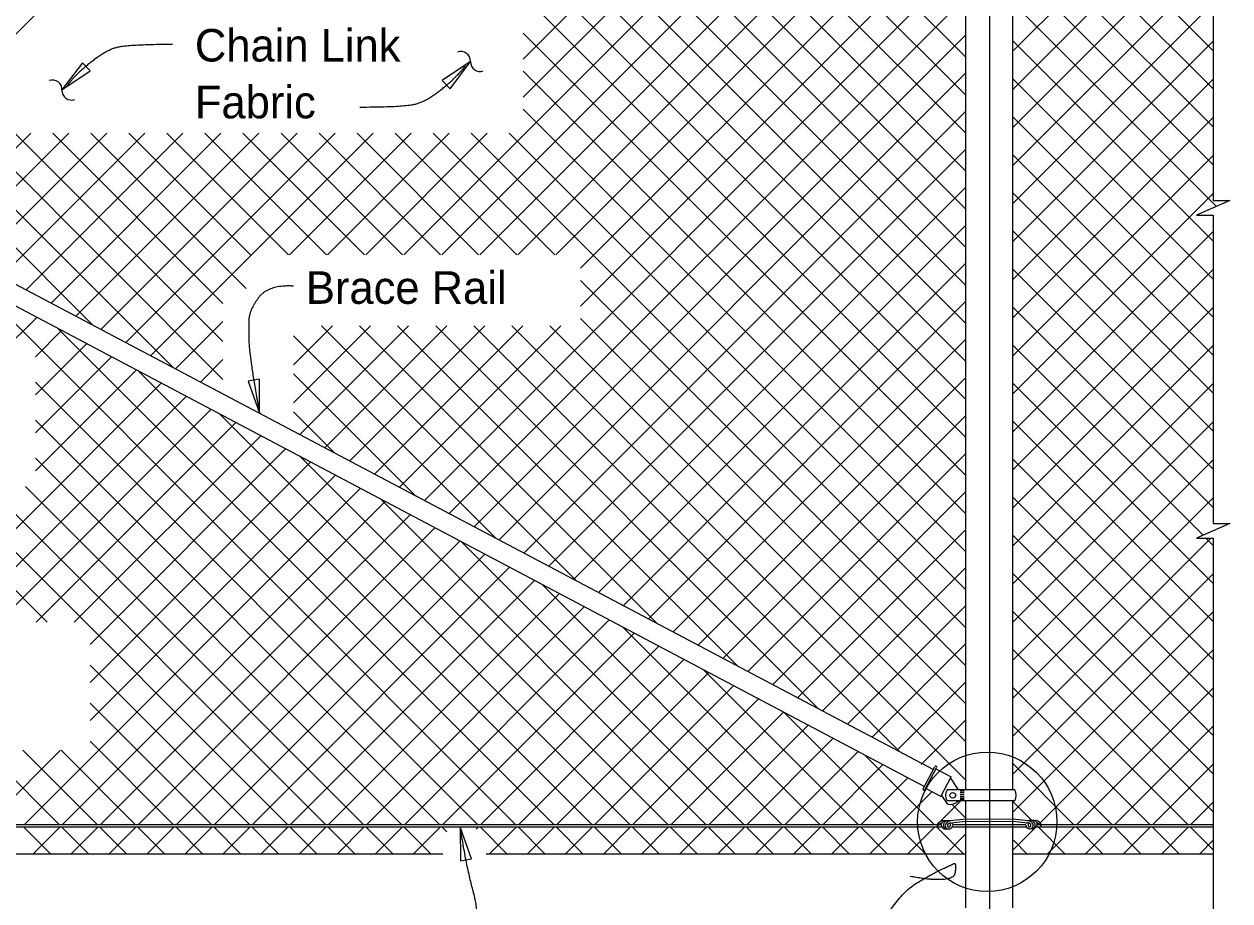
# Model space of a CAD drawing. Extents: x 0 to 72.1, y -7 to 30.
# Drawn here: x 16.24 to 23.71, y 18.9 to 24.33 of the extents above; entities that cross this region are included whole.
import ezdxf

# ---------------------------------------------------------------- set-up
doc = ezdxf.new("R2010")
doc.units = 0
for name, color, linetype in [('AdhocPoint_dp', 7, 'Continuous'), ('Border', 7, 'Continuous'), ('Patterning', 7, 'Continuous'), ('PlotBorder_dp', 7, 'Continuous'), ('SheetBorder_dp', 7, 'Continuous'), ('TextMisc', 7, 'Continuous'), ('TextStructures', 7, 'Continuous')]:
    doc.layers.add(name, color=color, linetype=linetype)

msp = doc.modelspace()

# ---------------------------------------------------------------- linework, layer by layer
at = {"layer": 'AdhocPoint_dp'}
for p, q in [((14.1214, 25.0085), (16.6644, 22.4655)), ((14.3571, 25.0085), (17.1643, 22.2013)), ((14.5928, 25.0085), (17.4733, 22.128)), ((14.8285, 25.0085), (17.4733, 22.3637)), ((15.1745, 23.2529), (16.9301, 25.0085)), ((18.5935, 22.9006), (20.7014, 25.0085)), ((18.8292, 22.9006), (20.9371, 25.0085)), ((18.8354, 25.0085), (22.0764, 21.7675)), ((19.0649, 22.9006), (21.1728, 25.0085)), ((19.0711, 25.0085), (22.0764, 22.0032)), ((19.3006, 22.9006), (21.4085, 25.0085)), ((19.3068, 25.0085), (22.0764, 22.2389)), ((19.3344, 23.8772), (20.4657, 25.0085)), ((19.3344, 24.1129), (20.23, 25.0085)), ((19.5363, 22.9006), (21.6442, 25.0085)), ((19.5363, 22.9006), (21.6442, 25.0085)), ((19.5425, 25.0085), (22.0764, 22.4746)), ((19.6891, 22.8178), (21.8799, 25.0085)), ((19.6891, 22.582), (22.0764, 24.9694)), ((19.7782, 25.0085), (22.0764, 22.7103)), ((20.0139, 25.0085), (22.0764, 22.946)), ((20.2496, 25.0085), (22.0764, 23.1818)), ((20.4853, 25.0085), (22.0764, 23.4175)), ((20.721, 25.0085), (22.0764, 23.6532)), ((20.9567, 25.0085), (22.0764, 23.8889)), ((21.1925, 25.0085), (22.0764, 24.1246)), ((22.3681, 23.9248), (23.4518, 25.0085)), ((22.3725, 24.165), (23.2161, 25.0085)), ((22.5286, 25.0085), (23.6092, 23.928)), ((22.7643, 25.0085), (23.6092, 24.1637)), ((22.3681, 24.9334), (23.6092, 23.6923)), ((22.3681, 23.6891), (23.6092, 24.9302)), ((18.7213, 21.3785), (22.0764, 24.7337)), ((22.3681, 24.6977), (23.6092, 23.4566)), ((22.3681, 23.4534), (23.6092, 24.6945)), ((18.8755, 21.297), (22.0764, 24.4979)), ((22.3681, 24.462), (23.6302, 23.1998)), ((22.3681, 23.2177), (23.6092, 24.4588)), ((19.0297, 21.2155), (22.0764, 24.2622)), ((19.3344, 24.2739), (22.0764, 21.5318)), ((22.3681, 24.2263), (23.6092, 22.9852)), ((22.3681, 22.982), (23.6092, 24.2231)), ((19.1839, 21.134), (22.0764, 24.0265)), ((19.3344, 24.0382), (22.0764, 21.2961)), ((22.3681, 23.9906), (23.6092, 22.7495)), ((22.3681, 22.7463), (23.6092, 23.9874)), ((19.3344, 23.8025), (22.0764, 21.0604)), ((19.3381, 21.0525), (22.0764, 23.7908)), ((22.3681, 23.7549), (23.6092, 22.5138)), ((22.3681, 22.5106), (23.6092, 23.7517)), ((15.6371, 23.0084), (16.2825, 23.6538)), ((15.7913, 22.9269), (16.5182, 23.6538)), ((15.7913, 22.9269), (16.5182, 23.6538)), ((15.9455, 22.8454), (16.7539, 23.6538)), ((15.9455, 22.8454), (16.7539, 23.6538)), ((16.0997, 22.7639), (16.9896, 23.6538)), ((16.0997, 22.7639), (16.9896, 23.6538)), ((16.2539, 22.6824), (17.2253, 23.6538)), ((16.2539, 22.6824), (17.2253, 23.6538)), ((16.4081, 22.6009), (17.461, 23.6538)), ((16.4189, 23.6538), (17.4733, 22.5994)), ((16.5623, 22.5194), (17.6967, 23.6538)), ((16.6546, 23.6538), (17.6177, 22.6907)), ((16.7166, 22.4379), (17.9324, 23.6538)), ((16.8708, 22.3564), (18.1681, 23.6538)), ((16.8903, 23.6538), (17.6435, 22.9006)), ((16.8903, 23.6538), (17.6435, 22.9006)), ((17.025, 22.2749), (18.4038, 23.6538)), ((17.126, 23.6538), (17.8792, 22.9006)), ((17.3617, 23.6538), (18.1149, 22.9006)), ((17.3617, 23.6538), (18.1149, 22.9006)), ((17.3617, 23.6538), (18.1149, 22.9006)), ((17.5974, 23.6538), (18.3506, 22.9006)), ((17.5974, 23.6538), (18.3506, 22.9006)), ((17.8331, 23.6538), (18.5863, 22.9006)), ((17.8864, 22.9006), (18.6395, 23.6538)), ((18.0688, 23.6538), (18.822, 22.9006)), ((18.1221, 22.9006), (18.8752, 23.6538)), ((18.3045, 23.6538), (19.0577, 22.9006)), ((18.3578, 22.9006), (19.1109, 23.6538)), ((18.5402, 23.6538), (19.2934, 22.9006)), ((18.7759, 23.6538), (19.5291, 22.9006)), ((19.0116, 23.6538), (22.0764, 20.589)), ((19.2473, 23.6538), (22.0764, 20.8247)), ((19.4923, 20.9711), (22.0764, 23.5551)), ((22.3681, 23.5192), (23.6092, 22.2781)), ((22.3681, 22.2749), (23.6092, 23.516)), ((19.6465, 20.8896), (22.0764, 23.3194)), ((22.3681, 23.2835), (23.6092, 22.0424)), ((22.3681, 22.0392), (23.6092, 23.2803)), ((19.8007, 20.8081), (22.0764, 23.0837)), ((22.3681, 23.0478), (23.6092, 21.8067)), ((22.3681, 21.8035), (23.6092, 23.0446)), ((19.9549, 20.7266), (22.0764, 22.848)), ((22.3681, 22.8121), (23.6092, 21.571)), ((22.3681, 21.5678), (23.6092, 22.8089)), ((19.6891, 22.7406), (22.0764, 20.3533)), ((15.9523, 22.7062), (19.2871, 19.3714)), ((20.1092, 20.6451), (22.0764, 22.6123)), ((22.3681, 22.5764), (23.6092, 21.3353)), ((22.3681, 21.3321), (23.6092, 22.5732)), ((16.1061, 22.2989), (16.3194, 22.5122)), ((19.6891, 22.5049), (22.0764, 20.1176)), ((16.3112, 22.2683), (16.4736, 22.4307)), ((16.4522, 22.442), (19.5228, 19.3714)), ((17.1792, 22.1934), (17.4733, 22.4876)), ((17.9108, 21.9823), (18.3883, 22.4597)), ((17.9108, 22.218), (18.1526, 22.4597)), ((17.9502, 21.786), (18.624, 22.4597)), ((18.0844, 22.4597), (19.6635, 20.8806)), ((18.0844, 22.4597), (19.6635, 20.8806)), ((18.1044, 21.7045), (18.8597, 22.4597)), ((18.2586, 21.623), (19.0954, 22.4597)), ((18.2586, 21.623), (19.0954, 22.4597)), ((18.3201, 22.4597), (20.1634, 20.6164)), ((18.4129, 21.5415), (19.3311, 22.4597)), ((18.5558, 22.4597), (20.6633, 20.3523)), ((18.5558, 22.4597), (20.6633, 20.3523)), ((18.5558, 22.4597), (20.6633, 20.3523)), ((18.5671, 21.46), (19.5668, 22.4597)), ((18.7915, 22.4597), (21.1631, 20.0881)), ((18.7915, 22.4597), (21.1631, 20.0881)), ((19.0272, 22.4597), (21.663, 19.824)), ((19.2629, 22.4597), (22.0764, 19.6462)), ((19.4986, 22.4597), (22.0764, 19.8819)), ((16.3112, 22.0326), (16.6278, 22.3492)), ((17.9108, 22.3976), (19.1637, 21.1447)), ((20.2634, 20.5636), (22.0764, 22.3766)), ((22.3681, 22.3406), (23.5466, 21.1621)), ((16.3112, 21.7969), (16.782, 22.2677)), ((22.3681, 21.0964), (23.6092, 22.3375)), ((17.3334, 22.112), (17.4733, 22.2519)), ((16.3112, 21.5612), (16.9363, 22.1862)), ((16.952, 22.1779), (19.7585, 19.3714)), ((17.9108, 22.1619), (18.6638, 21.4089)), ((20.4176, 20.4821), (22.0764, 22.1409)), ((15.6097, 20.6239), (17.0905, 22.1047)), ((16.3112, 22.1116), (19.0514, 19.3714)), ((22.3681, 22.1049), (23.6092, 20.8639)), ((22.3681, 20.8607), (23.6092, 22.1018)), ((15.8454, 20.6239), (17.2447, 22.0232)), ((16.0811, 20.6239), (17.3989, 21.9417)), ((17.4518, 21.9138), (19.9943, 19.3714)), ((17.9108, 21.9262), (18.164, 21.673)), ((20.5718, 20.4006), (22.0764, 21.9052)), ((16.3112, 21.8759), (18.8157, 19.3714)), ((16.3168, 20.6239), (17.5531, 21.8603)), ((22.3681, 21.8692), (23.6092, 20.6282)), ((22.3681, 20.625), (23.6092, 21.8661)), ((16.5525, 20.6239), (17.7073, 21.7788)), ((16.6499, 20.4856), (17.8615, 21.6973)), ((20.726, 20.3191), (22.0764, 21.6695)), ((16.3112, 21.6402), (18.58, 19.3714)), ((16.6499, 20.2499), (18.0157, 21.6158)), ((17.9517, 21.6496), (20.23, 19.3714)), ((22.3681, 21.6335), (23.6092, 20.3925)), ((22.3681, 20.3893), (23.6092, 21.6304)), ((16.6499, 20.0142), (18.1699, 21.5343)), ((15.5438, 21.4647), (16.3847, 20.6239)), ((15.7795, 21.4647), (17.8729, 19.3714)), ((16.0152, 21.4647), (18.1086, 19.3714)), ((16.2427, 19.3714), (18.3242, 21.4528)), ((16.2509, 21.4647), (18.3443, 19.3714)), ((16.4784, 19.3714), (18.4784, 21.3713)), ((18.4515, 21.3855), (20.4657, 19.3714)), ((20.8802, 20.2376), (22.0764, 21.4338)), ((22.3681, 21.3978), (23.6092, 20.1568)), ((22.3681, 20.1536), (23.6092, 21.3947)), ((16.7141, 19.3714), (18.6326, 21.2898)), ((16.9498, 19.3714), (18.7868, 21.2083)), ((21.0344, 20.1561), (22.0764, 21.1981)), ((22.3681, 21.1621), (23.6092, 19.921)), ((22.3681, 19.9179), (23.5945, 21.1443)), ((23.5644, 21.1443), (23.6092, 21.0996)), ((17.1855, 19.3714), (18.941, 21.1268)), ((18.9513, 21.1214), (20.7014, 19.3714)), ((17.4212, 19.3714), (19.0952, 21.0453)), ((17.6569, 19.3714), (19.2494, 20.9639)), ((21.1886, 20.0746), (22.0764, 20.9624)), ((22.3681, 20.9264), (23.6092, 19.6853)), ((22.3681, 19.6822), (23.6092, 20.9233)), ((17.8926, 19.3714), (19.4036, 20.8824)), ((19.4512, 20.8572), (20.9371, 19.3714)), ((18.1283, 19.3714), (19.5578, 20.8009)), ((18.364, 19.3714), (19.7121, 20.7194)), ((21.3428, 19.9931), (22.0764, 20.7267)), ((18.5997, 19.3714), (19.8663, 20.6379)), ((22.3681, 20.6907), (23.6092, 19.4496)), ((22.3681, 19.4465), (23.6092, 20.6876)), ((18.8354, 19.3714), (20.0205, 20.5564)), ((19.951, 20.5931), (21.1728, 19.3714)), ((19.0711, 19.3714), (20.1747, 20.4749)), ((21.497, 19.9116), (22.0764, 20.491)), ((22.3681, 20.455), (23.4518, 19.3714)), ((22.5375, 19.3802), (23.6092, 20.4519)), ((16.6499, 20.3587), (17.6372, 19.3714)), ((19.3068, 19.3714), (20.3289, 20.3934)), ((20.4509, 20.329), (21.4085, 19.3714)), ((19.5425, 19.3714), (20.4831, 20.3119)), ((21.6513, 19.8302), (22.0764, 20.2553)), ((19.7782, 19.3714), (20.6373, 20.2304)), ((22.3681, 20.2193), (23.2161, 19.3714)), ((22.7643, 19.3714), (23.6092, 20.2162)), ((16.6499, 20.123), (17.4015, 19.3714)), ((20.0139, 19.3714), (20.7915, 20.1489)), ((20.2496, 19.3714), (20.9457, 20.0674)), ((20.9507, 20.0648), (21.6442, 19.3714)), ((20.4853, 19.3714), (21.0999, 19.986)), ((21.7999, 19.7431), (22.0764, 20.0196)), ((22.3681, 19.9836), (22.9804, 19.3714)), ((23, 19.3714), (23.6092, 19.9805)), ((16.6499, 19.8873), (17.1658, 19.3714)), ((20.721, 19.3714), (21.2542, 19.9045)), ((15.9985, 19.8315), (16.4587, 19.3714)), ((16.007, 19.3714), (16.4663, 19.8306)), ((16.2343, 19.8315), (16.6944, 19.3714)), ((16.47, 19.8315), (16.9301, 19.3714)), ((20.9567, 19.3714), (21.4084, 19.823)), ((21.4505, 19.8007), (21.8799, 19.3714)), ((21.1925, 19.3714), (21.5626, 19.7415)), ((22.3681, 19.7479), (22.7446, 19.3714)), ((23.2357, 19.3714), (23.6092, 19.7448)), ((21.4282, 19.3714), (21.7168, 19.66)), ((21.6639, 19.3714), (21.8663, 19.5738)), ((21.9155, 19.3873), (22.0451, 19.5169)), ((22.3681, 19.5122), (22.4855, 19.3948)), ((23.4714, 19.3714), (23.6092, 19.5091)), ((21.9907, 19.4962), (22.0764, 19.4105)), ((16.2378, 19.3566), (16.4044, 19.1899)), ((16.297, 19.1899), (16.4637, 19.3566)), ((16.4735, 19.3566), (16.6401, 19.1899)), ((16.5327, 19.1899), (16.6994, 19.3566)), ((16.7092, 19.3566), (16.8758, 19.1899)), ((16.7684, 19.1899), (16.9351, 19.3566)), ((16.9449, 19.3566), (17.1115, 19.1899)), ((17.0041, 19.1899), (17.1708, 19.3566)), ((17.1806, 19.3566), (17.3472, 19.1899)), ((17.2398, 19.1899), (17.4065, 19.3566)), ((17.4163, 19.3566), (17.5829, 19.1899)), ((17.4755, 19.1899), (17.6422, 19.3566)), ((17.652, 19.3566), (17.8186, 19.1899)), ((17.7112, 19.1899), (17.8779, 19.3566)), ((17.8877, 19.3566), (18.0543, 19.1899)), ((17.9469, 19.1899), (18.1136, 19.3566)), ((18.1234, 19.3566), (18.2901, 19.1899)), ((18.1826, 19.1899), (18.3493, 19.3566)), ((18.3591, 19.3566), (18.5258, 19.1899)), ((18.4183, 19.1899), (18.585, 19.3566)), ((18.5948, 19.3566), (18.7615, 19.1899)), ((18.654, 19.1899), (18.8207, 19.3566)), ((18.8305, 19.3566), (18.8616, 19.3255)), ((19.0423, 19.3425), (19.0564, 19.3566)), ((19.0662, 19.3566), (19.2329, 19.1899)), ((19.1254, 19.1899), (19.2921, 19.3566)), ((19.3019, 19.3566), (19.4686, 19.1899)), ((19.3611, 19.1899), (19.5278, 19.3566)), ((19.5376, 19.3566), (19.7043, 19.1899)), ((19.5968, 19.1899), (19.7635, 19.3566)), ((19.7733, 19.3566), (19.94, 19.1899)), ((19.8325, 19.1899), (19.9992, 19.3566)), ((20.009, 19.3566), (20.1757, 19.1899)), ((20.0682, 19.1899), (20.2349, 19.3566)), ((20.2447, 19.3566), (20.4114, 19.1899)), ((20.3039, 19.1899), (20.4706, 19.3566)), ((20.4804, 19.3566), (20.6471, 19.1899)), ((20.5396, 19.1899), (20.7063, 19.3566)), ((20.7161, 19.3566), (20.8828, 19.1899)), ((20.7753, 19.1899), (20.942, 19.3566)), ((20.9518, 19.3566), (21.1185, 19.1899)), ((21.011, 19.1899), (21.1777, 19.3566)), ((21.1875, 19.3566), (21.3542, 19.1899)), ((21.2467, 19.1899), (21.4134, 19.3566)), ((21.4232, 19.3566), (21.5899, 19.1899)), ((21.4824, 19.1899), (21.6491, 19.3566)), ((21.6589, 19.3566), (21.8256, 19.1899)), ((21.7181, 19.1899), (21.8848, 19.3566)), ((21.8946, 19.3566), (22.0613, 19.1899)), ((21.8996, 19.3714), (21.9031, 19.3749)), ((21.8996, 19.3714), (21.9031, 19.3749)), ((22.5237, 19.3566), (22.6904, 19.1899)), ((22.5829, 19.1899), (22.7496, 19.3566)), ((22.7594, 19.3566), (22.9261, 19.1899)), ((22.8186, 19.1899), (22.9853, 19.3566)), ((22.9951, 19.3566), (23.1618, 19.1899)), ((23.0543, 19.1899), (23.221, 19.3566)), ((23.2308, 19.3566), (23.3975, 19.1899)), ((23.29, 19.1899), (23.4567, 19.3566)), ((23.4665, 19.3566), (23.6092, 19.2139)), ((21.9538, 19.1899), (22.0764, 19.3125)), ((22.3681, 19.2108), (22.5064, 19.3491)), ((22.3713, 19.2733), (22.4547, 19.1899)), ((23.5257, 19.1899), (23.6092, 19.2734))]:
    msp.add_line(p, q, dxfattribs=at)
at = {"layer": 'Border'}
for points in [[(23.6092, 25.192), (23.6092, 23.2357), (23.7126, 23.2357), (23.6092, 23.1907), (23.5059, 23.1457), (23.6092, 23.1457), (23.6092, 22.2521)], [(23.6092, 22.2521), (23.6092, 21.2344), (23.7126, 21.2344), (23.6092, 21.1894), (23.5059, 21.1444), (23.6092, 21.1444), (23.6092, 18.94)], [(23.6092, 19.19), (23.6092, 17.3392), (23.7126, 17.3392), (23.6092, 17.2942), (23.5059, 17.2492), (23.6092, 17.2492), (23.6092, 15.3986)]]:
    msp.add_lwpolyline(points, dxfattribs=at)
for points in [[(16.4755, 23.9211), (16.6508, 24.039), (16.6022, 24.0902)], [(19.0077, 24.0972), (18.8324, 23.9793), (18.881, 23.9282)], [(17.7, 21.9183), (17.6996, 22.1296), (17.6301, 22.1177)], [(18.9433, 19.3567), (18.9449, 19.1455), (19.0143, 19.1578)]]:
    msp.add_lwpolyline(points, close=True, dxfattribs=at)
msp.add_circle((22.2094, 19.3871), 0.4318, dxfattribs=at)
for centre, start, end in [((18.9475, 24.1), 357.71778, 109.44499), ((19.0667, 24.0952), 177.71778, 289.44499), ((16.4164, 23.923), 357.71778, 109.44499), ((16.5355, 23.9183), 177.71778, 289.44499)]:
    msp.add_arc(centre, 0.0596, start, end, dxfattribs=at)
for points in [[(17.1607, 24.2028), (16.8705, 24.2028), (16.7339, 24.158), (16.5469, 24.0044), (16.5086, 23.9468)], [(18.3224, 23.8155), (18.6125, 23.8155), (18.7491, 23.8603), (18.9361, 24.0139), (18.9745, 24.0715)], [(17.91, 22.7062), (17.7535, 22.7144), (17.6354, 22.5559), (17.6325, 22.4348), (17.6371, 22.267), (17.6999, 21.9183)], [(18.6319, 18.6097), (18.8548, 18.6061), (18.9397, 18.6451), (19.0705, 18.7938), (18.9856, 19.0912), (18.9432, 19.3566)], [(20.5616, 17.0529), (21.3209, 17.019), (21.3812, 18.0751), (21.4565, 18.573), (21.6676, 18.9501), (21.9063, 19.0851), (21.9808, 19.1169), (22.0203, 19.1386), (21.998, 19.0004), (21.7311, 19.049)]]:
    msp.add_open_spline(points, degree=2, dxfattribs=at)
at = {"layer": 'Patterning'}
for p, q in [((22.0764, 19.3714), (22.3681, 19.3714)), ((22.0764, 19.3566), (22.3681, 19.3566))]:
    msp.add_line(p, q, dxfattribs=at)
at = {"layer": 'PlotBorder_dp'}
for p, q in [((22.0764, 19.5847), (22.0764, 25.2299)), ((22.3681, 19.5847), (22.3681, 25.2299)), ((21.8748, 19.712), (12.6252, 24.6)), ((21.8189, 19.606), (12.5692, 24.494)), ((21.8113, 19.5918), (21.8838, 19.7289)), ((21.8232, 19.5855), (21.8956, 19.7227)), ((21.8915, 19.7147), (21.9858, 19.6649)), ((21.9221, 19.5443), (21.9858, 19.6649)), ((21.9816, 19.6569), (22.0285, 19.5852)), ((21.9221, 19.5443), (21.8278, 19.5942)), ((22.3794, 19.5847), (21.9597, 19.5847)), ((22.0421, 19.5784), (22.0655, 19.5784)), ((21.9255, 19.5509), (21.9603, 19.4978)), ((22.3793, 19.5169), (21.9597, 19.5169)), ((22.0421, 19.5686), (22.0655, 19.5686)), ((22.0421, 19.5569), (22.0655, 19.5569)), ((22.0421, 19.5451), (22.0655, 19.5451)), ((22.0421, 19.5343), (22.0655, 19.5343)), ((22.0421, 19.5247), (22.0655, 19.5247)), ((22.0764, 18.8548), (22.0764, 19.5169)), ((22.3681, 18.8548), (22.3681, 19.5169)), ((12.5301, 19.3566), (21.9279, 19.3566)), ((12.5315, 19.3714), (21.9013, 19.3714)), ((21.9112, 19.3714), (21.9243, 19.3714)), ((21.9112, 19.3714), (21.9243, 19.3714)), ((22.0764, 19.404), (21.9815, 19.3929)), ((22.0764, 19.404), (21.9815, 19.3929)), ((22.0764, 19.3895), (21.9838, 19.3799)), ((22.0764, 19.3895), (21.9838, 19.3799)), ((21.9928, 19.3566), (22.0764, 19.3566)), ((21.9928, 19.3566), (22.0764, 19.3566)), ((21.9942, 19.3714), (22.0764, 19.3714)), ((21.9942, 19.3714), (22.0764, 19.3714)), ((22.0764, 19.404), (22.3676, 19.4057)), ((22.0764, 19.3895), (22.3676, 19.3911)), ((22.3676, 19.4057), (22.4619, 19.3945)), ((22.3676, 19.3911), (22.4597, 19.3817)), ((22.3681, 19.3714), (22.4485, 19.3714)), ((22.3681, 19.3566), (22.4511, 19.3566)), ((22.513, 19.3566), (23.6091, 19.3566)), ((22.5188, 19.3714), (22.5341, 19.3714)), ((22.5425, 19.3714), (23.6091, 19.3714))]:
    msp.add_line(p, q, dxfattribs=at)
for centre, start, end in [((21.8899, 19.7259), 332.14902, 152.14902), ((21.8174, 19.5887), 152.14902, 332.14902)]:
    msp.add_arc(centre, 0.00673, start, end, dxfattribs=at)
for centre, major_axis, ratio, start_param, end_param in [((22.0289, 19.551), (-0.0776, 0), 0.957868, 5.810211, 6.75616), ((22.3103, 19.5509), (0.0776, 0), 0.957868, 5.807767, 6.754779), ((21.9769, 19.5661), (0.0647, -0.0342), 0.957868, 4.95193, 6.011789), ((21.9355, 19.3571), (0.0373, 0), 0.957868, 1.486836, 3.108042), ((21.9355, 19.3571), (0.0373, 0), 0.957868, 1.486836, 3.108042), ((21.9566, 19.3174), (-0.0724, 0), 0.957868, 5.162149, 5.652106), ((21.9566, 19.3174), (-0.0724, 0), 0.957868, 5.162149, 5.652106), ((21.9491, 19.369), (-0.0249, 0), 0.957868, 6.009018, 7.089857), ((21.9491, 19.369), (-0.0249, 0), 0.957868, 6.009018, 7.089857), ((21.948, 19.3716), (0.023, 0), 0.957868, 1.29026, 2.970541), ((21.948, 19.3716), (0.023, 0), 0.957868, 1.29026, 2.970541), ((21.9505, 19.365), (0.0231, 0), 0.957868, 3.779554, 4.879821), ((21.9505, 19.365), (0.0231, 0), 0.957868, 3.779554, 4.879821), ((21.9667, 19.3662), (0.0295, 0), 0.957868, 1.220941, 4.039556), ((21.9667, 19.3662), (0.0295, 0), 0.957868, 1.220941, 4.039556), ((21.9802, 19.368), (-0.0303, -0.0108), 0.724765, 4.35367, 6.324556), ((21.9802, 19.368), (-0.0303, -0.0108), 0.724765, 4.35367, 6.324556), ((21.9701, 19.3594), (0.0206, -0.0021), 0.798607, 3.333154, 5.220153), ((21.9701, 19.3594), (0.0206, -0.0021), 0.798607, 3.333154, 5.220153), ((21.9769, 19.3639), (-0.0139, 0), 0.957868, 5.22362, 6.905413), ((21.9769, 19.3639), (-0.0139, 0), 0.957868, 5.22362, 6.905413), ((21.9712, 19.3615), (-0.00795, 0), 0.957868, 6.140374, 9.314262), ((21.9712, 19.3615), (-0.00795, 0), 0.957868, 6.140374, 9.314262), ((21.9853, 19.3551), (-0.0259, 0), 0.957868, 4.777514, 5.62749), ((21.9853, 19.3551), (-0.0259, 0), 0.957868, 4.777514, 5.62749), ((21.9695, 19.3673), (0.0119, 0), 0.957868, 5.725876, 7.416677), ((21.9695, 19.3673), (0.0119, 0), 0.957868, 5.725876, 7.416677), ((21.9695, 19.3673), (0.0119, 0), 0.957868, 5.639684, 5.723117), ((21.9695, 19.3673), (0.0119, 0), 0.957868, 5.639684, 5.723117), ((21.9698, 19.3661), (0.0251, 0), 0.957868, 5.531357, 6.227833), ((21.9698, 19.3661), (0.0251, 0), 0.957868, 5.531357, 6.227833), ((21.9698, 19.3661), (0.0251, 0), 0.957868, 0.407687, 0.609214), ((21.9698, 19.3661), (0.0251, 0), 0.957868, 0.407687, 0.609214), ((22.4733, 19.3678), (-0.0251, 0), 0.957868, 0.055352, 0.751829), ((22.4733, 19.3678), (-0.0251, 0), 0.957868, 5.673972, 5.875498), ((22.4803, 19.3799), (-0.0391, 0), 0.957868, 0.863445, 1.200597), ((22.4628, 19.3697), (0.0303, -0.0108), 0.724765, 6.241815, 8.212701), ((22.4578, 19.3568), (0.0259, 0), 0.957868, 0.655696, 1.505671), ((22.4735, 19.3691), (-0.0119, 0), 0.957868, 5.149694, 6.840495), ((22.4735, 19.3691), (-0.0119, 0), 0.957868, 0.560069, 0.643501), ((22.4718, 19.3633), (0.00795, 0), 0.957868, 3.252108, 6.425997), ((22.4729, 19.3611), (-0.0206, -0.0021), 0.798607, 1.063032, 2.950031), ((22.4763, 19.368), (-0.0295, 0), 0.957868, 2.243629, 5.062245), ((22.4661, 19.3657), (0.0139, 0), 0.957868, 5.660958, 7.342751), ((22.495, 19.3733), (-0.023, 0), 0.957868, 3.312645, 4.992926), ((22.4925, 19.3668), (-0.0231, 0), 0.957868, 1.403365, 2.503632), ((22.5075, 19.3589), (-0.0373, 0), 0.957868, 3.175144, 4.79635), ((22.4939, 19.3708), (0.0249, 0), 0.957868, 5.476514, 6.557353), ((22.4864, 19.3192), (0.0724, 0), 0.957868, 0.631079, 1.121037), ((21.9566, 19.3594), (0.0206, -0.0021), 0.798607, 4.32653, 5.220153), ((21.9566, 19.3594), (0.0206, -0.0021), 0.798607, 4.32653, 5.220153), ((21.9627, 19.3781), (0.0391, 0), 0.957868, 5.082588, 5.41974), ((21.9627, 19.3781), (0.0391, 0), 0.957868, 5.082588, 5.41974), ((22.4864, 19.3611), (-0.0206, -0.0021), 0.798607, 1.063032, 1.956656)]:
    msp.add_ellipse(centre, major_axis=major_axis, ratio=ratio, start_param=start_param, end_param=end_param, dxfattribs=at)
msp.add_ellipse((21.9956, 19.5514), major_axis=(0.0178, 0), ratio=0.957868, dxfattribs=at)
at = {"layer": 'SheetBorder_dp'}
msp.add_line((22.2222, 27.5581), (22.2222, 16.7178), dxfattribs=at)
at = {"layer": 'TextMisc'}
for p, q in [((12.3681, 19.1899), (18.8364, 19.1899)), ((19.1053, 19.1899), (22.0764, 19.1899)), ((22.3681, 19.1899), (23.6091, 19.1899))]:
    msp.add_line(p, q, dxfattribs=at)

# ---------------------------------------------------------------- texts
at = {"layer": 'Border'}
for s, p in [('Chain Link ', (17.2995, 24.0975)), ('Fabric ', (17.2995, 23.7455))]:
    msp.add_text(s, height=0.2016, dxfattribs=at).set_placement(p)
at = {"layer": 'TextStructures'}
msp.add_text('Brace Rail', height=0.2016, dxfattribs=at).set_placement((17.9874, 22.5963))

doc.saveas('drawing.dxf')
